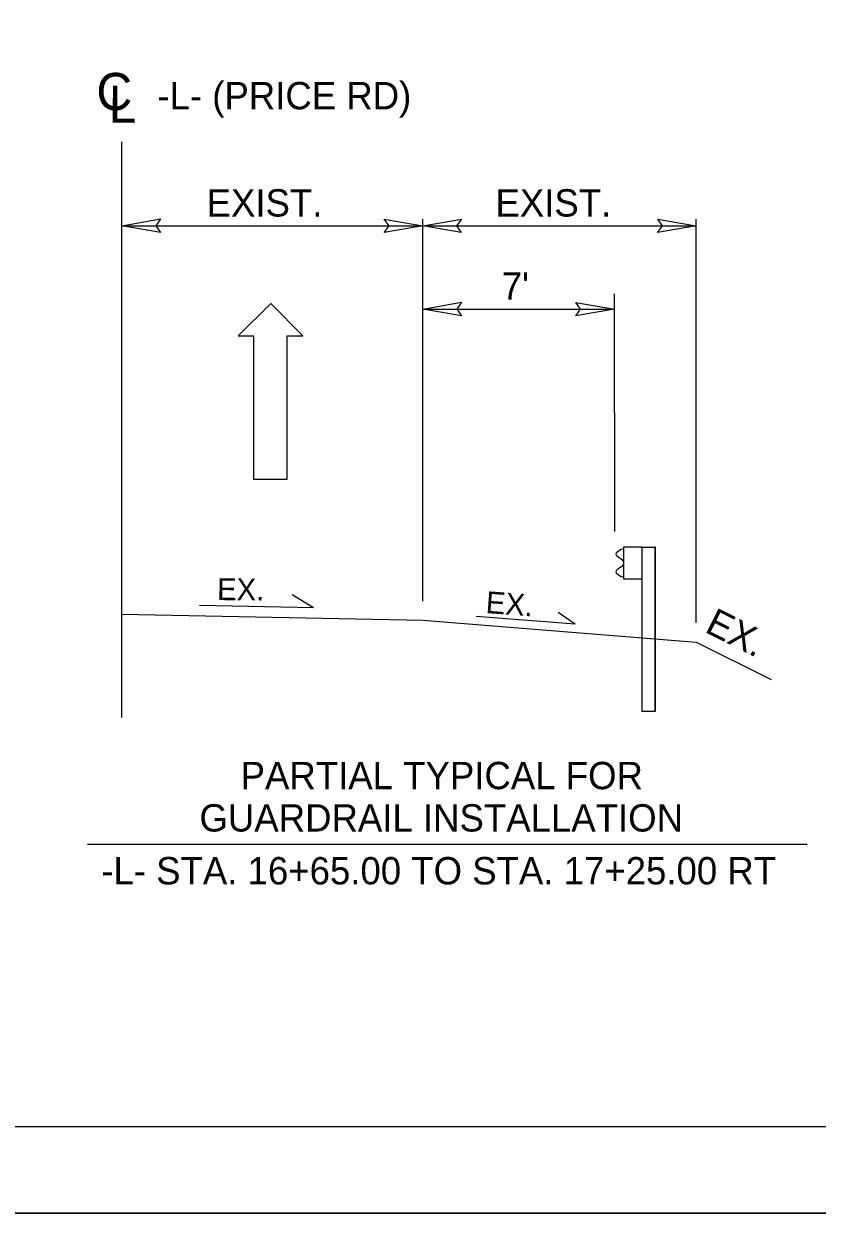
# Model space of a CAD drawing. Extents: x 1184121 to 1184397, y 1246506 to 1246661.
# Drawn here: x 1184251.75 to 1184280.76, y 1246505.71 to 1246549.22 of the extents above; entities that cross this region are included whole.
import ezdxf

# ---------------------------------------------------------------- set-up
doc = ezdxf.new("R2010")
doc.units = 0
for name, color, linetype in [('P_RDY_DXS_Guardrail_Cell', 7, 'Continuous'), ('Sheet Data Field CELL', 7, 'Continuous'), ('Sheet Plan CELL', 7, 'Continuous'), ('Sheet Plot Border Outside CELL', 7, 'Continuous'), ('z - Construction', 7, 'Continuous')]:
    doc.layers.add(name, color=color, linetype=linetype)

msp = doc.modelspace()

# ---------------------------------------------------------------- linework, layer by layer
at = {"layer": 'P_RDY_DXS_Guardrail_Cell'}
for p, q in [((1184273.574, 1246529.978), (1184273.437, 1246529.881)), ((1184273.438, 1246529.752), (1184273.646, 1246529.608)), ((1184273.675, 1246529.999), (1184273.588, 1246529.983)), ((1184274.347, 1246530.079), (1184273.68, 1246530.079)), ((1184273.68, 1246530.079), (1184273.68, 1246528.912)), ((1184274.347, 1246530.079), (1184274.847, 1246530.079)), ((1184274.363, 1246530.079), (1184274.347, 1246530.079)), ((1184274.347, 1246530.079), (1184274.347, 1246524.079)), ((1184274.363, 1246524.079), (1184274.363, 1246530.079)), ((1184274.847, 1246530.079), (1184274.831, 1246530.079)), ((1184274.831, 1246530.079), (1184274.831, 1246524.079)), ((1184274.847, 1246524.079), (1184274.847, 1246530.079)), ((1184273.646, 1246529.383), (1184273.438, 1246529.239)), ((1184273.68, 1246529.543), (1184273.68, 1246529.495)), ((1184273.68, 1246529.495), (1184273.68, 1246529.447)), ((1184273.437, 1246529.11), (1184273.574, 1246529.013)), ((1184273.588, 1246529.007), (1184273.675, 1246528.992)), ((1184273.68, 1246528.912), (1184274.347, 1246528.912)), ((1184274.347, 1246524.079), (1184274.847, 1246524.079)), ((1184274.347, 1246524.079), (1184274.363, 1246524.079)), ((1184274.831, 1246524.079), (1184274.847, 1246524.079))]:
    msp.add_line(p, q, dxfattribs=at)
for centre, radius, start, end in [((1184273.483, 1246529.816), 0.0787, 125.2976, 235.3478), ((1184273.593, 1246529.951), 0.0328, 100, 125.2976), ((1184273.601, 1246529.543), 0.0787, 0.02, 55.3478), ((1184273.601, 1246529.447), 0.0787, 304.6522, 359.98), ((1184273.483, 1246529.174), 0.0787, 124.6522, 234.7024), ((1184273.593, 1246529.039), 0.0328, 234.7024, 260)]:
    msp.add_arc(centre, radius, start, end, dxfattribs=at)
at = {"layer": 'Sheet Data Field CELL'}
for p, q in [((1184255.339, 1246523.839), (1184255.339, 1246544.9)), ((1184266.339, 1246528.102), (1184266.339, 1246542.078)), ((1184276.339, 1246527.302), (1184276.339, 1246542.078)), ((1184255.339, 1246541.83), (1184266.339, 1246541.83)), ((1184266.339, 1246541.83), (1184276.339, 1246541.829)), ((1184273.367, 1246530.649), (1184273.346, 1246539.343)), ((1184260.785, 1246538.988), (1184259.585, 1246537.806)), ((1184261.948, 1246537.806), (1184260.785, 1246538.988)), ((1184266.347, 1246538.784), (1184273.347, 1246538.784)), ((1184259.585, 1246537.806), (1184260.148, 1246537.806)), ((1184260.148, 1246537.806), (1184260.148, 1246532.556)), ((1184261.385, 1246532.556), (1184261.385, 1246537.806)), ((1184261.385, 1246537.806), (1184261.948, 1246537.806)), ((1184260.148, 1246532.556), (1184261.385, 1246532.556)), ((1184262.34, 1246527.852), (1184261.557, 1246528.325)), ((1184255.339, 1246527.621), (1184266.339, 1246527.401)), ((1184262.34, 1246527.852), (1184258.176, 1246527.935)), ((1184271.913, 1246527.262), (1184271.293, 1246527.69)), ((1184266.339, 1246527.401), (1184276.339, 1246526.601)), ((1184271.913, 1246527.262), (1184268.288, 1246527.535)), ((1184276.339, 1246526.601), (1184279.085, 1246525.229)), ((1184254.079, 1246519.205), (1184280.398, 1246519.205))]:
    msp.add_line(p, q, dxfattribs=at)
for points in [[(1184256.745, 1246541.587), (1184255.339, 1246541.83), (1184256.753, 1246542.08), (1184256.573, 1246541.83)], [(1184264.933, 1246542.072), (1184266.339, 1246541.83), (1184264.925, 1246541.58), (1184265.105, 1246541.83)], [(1184267.745, 1246541.587), (1184266.339, 1246541.83), (1184267.753, 1246542.079), (1184267.573, 1246541.83)], [(1184274.933, 1246542.072), (1184276.339, 1246541.829), (1184274.925, 1246541.58), (1184275.105, 1246541.829)], [(1184267.753, 1246538.541), (1184266.347, 1246538.784), (1184267.761, 1246539.034), (1184267.581, 1246538.784)], [(1184271.941, 1246539.026), (1184273.347, 1246538.784), (1184271.933, 1246538.534), (1184272.113, 1246538.784)]]:
    msp.add_lwpolyline(points, close=True, dxfattribs=at)
at = {"layer": 'Sheet Plan CELL'}
msp.add_line((1184126.181, 1246508.875), (1184358.419, 1246508.875), dxfattribs=at)
at = {"layer": 'Sheet Plot Border Outside CELL'}
msp.add_lwpolyline([(1184121.05, 1246660.53), (1184360.324, 1246660.53), (1184360.324, 1246505.708), (1184121.05, 1246505.708)], close=True, dxfattribs=at)
at = {"layer": 'z - Construction'}
msp.add_line((1184121.05, 1246505.708), (1184360.324, 1246505.708), dxfattribs=at)

# ---------------------------------------------------------------- texts
at = {"layer": 'Sheet Data Field CELL'}
for s, height, p in [('C', 1.36, (1184254.402, 1246546.064)), ('-L- (PRICE RD)', 1, (1184256.634, 1246546.094)), ('PARTIAL TYPICAL FOR', 1, (1184259.677, 1246521.22)), ('GUARDRAIL INSTALLATION', 1, (1184258.172, 1246519.671))]:
    msp.add_text(s, height=height, dxfattribs=at).set_placement(p)
for s, height, rotation, p in [('L', 1.361, 359.9469, (1184254.854, 1246545.599)), ('EXIST.', 1, 359.9998, (1184258.434, 1246542.17)), ('EXIST.', 1, 359.9998, (1184268.996, 1246542.17)), ("7'", 1, 359.9998, (1184269.225, 1246539.124)), ('EX.', 0.8, 359.4598, (1184258.814, 1246528.138)), ('EX.', 0.8, 355.7746, (1184268.623, 1246527.666)), ('EX.', 1, 333.4348, (1184276.613, 1246526.986)), ('-L- STA. 16+65.00 TO STA. 17+25.00 RT', 1, 0.0002, (1184254.583, 1246517.737))]:
    msp.add_text(s, height=height, rotation=rotation, dxfattribs=at).set_placement(p)

doc.saveas('drawing.dxf')
